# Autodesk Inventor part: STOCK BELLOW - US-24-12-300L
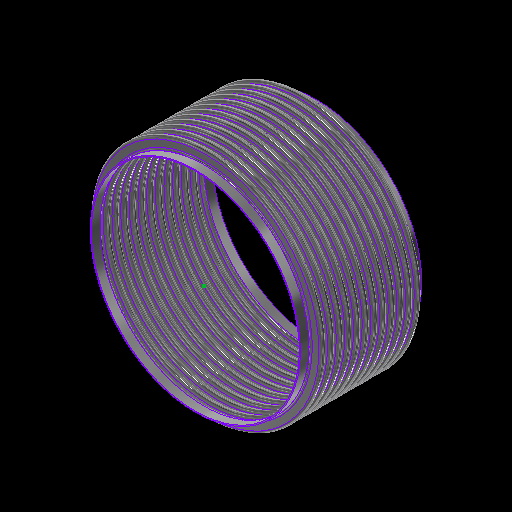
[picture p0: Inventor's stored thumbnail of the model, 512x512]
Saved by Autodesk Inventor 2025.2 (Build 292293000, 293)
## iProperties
Category: 16 GA (0.060 THICK)
RuleStatus: InUse
Created: 2024-01
Part Number: STOCK BELLOW - US-24-12-300L
Project: =STOCK BELLOWS: <Stock Number><SFILL>
Material: ASTM A240-304
Description: =STOCK BELLOWS: <Stock Number>, <SID_> I.D., <SOD_> O.D., <SPLY_> PLY, <Category>, <SNET_CONS> CONS.<PITCH_><STANGENT_> TANGENT<SFILL>
Document SubType Name: Sheet Metal
Designer: GS
Stock Number: U.S-24-12-300L
Surface Area: 40335 cm^2
Volume: 6093.4 cm^3
Sheet Metal Rule: Default
Appearance: STAINLESS STEEL
Mass: 49096.3 g
Density: 8.05729 g/cm^3
THK: 0.036
ID: 3.500
OD: 4.250
CONS_: 2
PITCH: 0.500
TANGENT: 0.500
BELLOWS_UPSET: 0.000
d79: 1.000
d82: 1.000
d83: 26.000
d84: 24.000
d174: 8
d214: 8
STHK_: 0.060
SID_: 24.000
SOD_: 26.750
SPITCH_: 1.000
STANGENT__: 1.000
SBELLOWS_UPSET_: 0.000
SDIFF_TAN: 1.000
d252: 2
d275: 2
d287: 0.050
d289: 0.500
d290: 0.000
SOD_NECK: 24 1/4
PLY: 1
PSET: 4.178
PBAR: 1.035
COUNTER: 1.500
NET_TUBE: 3.071
CONS: 2
S_CONS: 0
NET_CONS: 2
ID_M: 88.90 mm
OD_M: 107.95 mm
THK_M: 0.91 mm
ID_U: 3.500 in
OD_U: 4.250 in
THK_U: 0.036 in
TANGENT2: 0.500
TAN_TO_TAN: 1.000 in
d80: 2.571
d81: 10
SID: 2.375
SCONS_: 12
SPITCH: 0.250
STANGENT_: 1.000
SBELLOWS_UPSET: 0.000
SNET_CONS: 12
SS_CONS: 0
SCONS: 8
d190: 8
d191: 1
d192: 1
d193: 8
d194: 0
SIZE: 24.00
PRESSURE: 300
d230: 8
STANGENT: 4.000
SPLY_: 2
d233: 8
d234: 0
d263: 2
d265: 1
d268: 2
d269: 0
d286: 2
d288: 1
d291: 2
d292: 0
SREROLL: 0.750
BLETP: 1.000 ul
PRES_Copy: 85
MATTABLE: 20 GA (0.036 THICK)
PART_NUMBER: U.S-24-12-300L
PITCH_: =, <SPITCH_> PITCH,
CFILL: .
SFILL: .
MESH: ,
COMP: 2.41
EXT: 1.21
LAT: 0.35
ANG: 573
ASR: 6931
LSR: 46487
ANSR: 9736
PRES: 300
COMPM: 24.1
EXTM: 12.05
LATM: 3.50
ASRM: 1213.826
PRESM: 20.684
LSRM: 8141.268
ANSRM: 1705.066
TEMPMIN: 20
TEMPMAX: 800
TEMPMINM: -7
TEMPMAXM: 427
WEIGHTM: 49.096
WEIGHT: 108.239
Author: GS
Keywords: 20 GA (0.036 THICK)
Comments: =STOCK BELLOW - <STOCK NUMBER>
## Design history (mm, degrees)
sketch "Sketch2"
  geometry: L1 (0, -177.245)-(0, 562.856) reference; L2 (45.364, 0)-(44.45, 0); L3 (48.082, -2.718)-(50.343, -2.718); L4 (48.082, -3.632)-(50.343, -3.632); L5 (50.343, -9.982)-(48.082, -9.982); L6 (50.343, -9.068)-(48.082, -9.068); L7 (45.364, -12.7)-(44.45, -12.7); L8 (48.082, 0)-(48.082, -12.7); L9 (50.343, -6.35)-(53.975, -6.35); L10 (44.45, 0)-(44.45, -12.7); L11 (20.376, 102.841)-(20.376, 101.926); L12 (58.262, 457.127)-(58.262, 349.177); L13 (58.262, 444.427)-(58.262, 336.477); L14 (93.133, -58.817)-(93.133, -71.517); L15 (118.746, -66.401)-(118.746, -66.401); L16 (50.343, -9.068)-(50.343, -9.982); L17 (48.082, -9.068)-(48.082, -9.982); L18 (48.082, -9.525)-(50.343, -9.525); L19 (53.975, 0)-(53.975, -12.7); L20 (-50.343, -9.068)-(-50.343, -9.982); L21 (-50.343, -2.718)-(-48.082, -2.718); L22 (-50.343, -3.632)-(-48.082, -3.632); L23 (-48.082, -9.068)-(-50.343, -9.068); L24 (-50.343, -9.525)-(-48.082, -9.525); L25 (-48.082, -9.982)-(-50.343, -9.982); L26 (-48.082, -9.068)-(-48.082, -9.982); L27 (-44.45, 0.653)-(-44.45, -12.047); L28 (-48.082, -6.35)-(-44.45, -6.35); L29 (-50.343, 0.653)-(-50.343, -12.7); L30 (-53.061, 0)-(-53.975, 0); L31 (-53.975, 0)-(-53.975, -12.7); L32 (-53.061, -12.7)-(-53.975, -12.7); A1 r 2.718 centre (48.082, 0) between (45.364, 0) and (48.082, -2.718); A2 r 3.632 centre (48.082, 0) between (44.45, 0) and (48.082, -3.632); A3 r 3.632 centre (50.343, -6.35) between (50.343, -9.982) and (50.343, -2.718); A4 r 2.718 centre (50.343, -6.35) between (50.343, -9.068) and (50.343, -3.632); A5 r 2.718 centre (48.082, -12.7) between (48.082, -9.982) and (45.364, -12.7); A6 r 3.632 centre (48.082, -12.7) between (48.082, -9.068) and (44.45, -12.7); A7 r 3.175 centre (50.343, -6.35) between (50.343, -9.525) and (53.518, -6.35); A8 r 3.175 centre (48.082, -12.7) between (48.082, -9.525) and (44.907, -12.7); A9 r 2.718 centre (-50.343, -12.7) between (-50.343, -9.982) and (-53.061, -12.7); A10 r 2.718 centre (-48.082, -6.35) between (-48.082, -9.068) and (-48.082, -3.632); A11 r 3.175 centre (-48.082, -6.35) between (-48.082, -9.525) and (-44.907, -6.35); A12 r 3.632 centre (-48.082, -6.35) between (-48.082, -9.982) and (-48.082, -2.718); A13 r 3.175 centre (-50.343, -12.7) between (-50.343, -9.525) and (-53.518, -12.7); A14 r 3.632 centre (-50.343, -12.7) between (-50.343, -9.068) and (-53.975, -12.7); A15 r 2.718 centre (-50.343, 0) between (-53.061, 0) and (-50.343, -2.718); A16 r 3.632 centre (-50.343, 0) between (-53.975, 0) and (-50.343, -3.632); 10 further points
  constraints: 62 end point, 38 point on circle, 20 tangent, 16 centre point, 12 parallel, 9 midpoint, 7 vertical, 6 coincident, 6 concentric, 6 point on line, 4 equal radius, 4 perpendicular, 3 horizontal, 1 collinear, 1 horizontal alignment, 10 other
  dimensions: "THK" = 0.9144 distance of L11.start L11.end; "ID" = 88.9 distance of L11.end point (20.376, 13.026); "OD" = 107.95 distance of L12.start L12.end; "PITCH" = 12.7 distance of L12.start L13.start; "TANGENT" = 12.7 distance of L14.start L14.end; "BELLOWS_UPSET" = 0 distance of L15.start L15.end; "d43" = 88.9 diameter of L10 L1 (= ID); "d44" = 107.95 diameter of L9.end L1 (= OD); "d45" = 0.9144 distance between parallel lines of L5 L6 (computed from THK, PLY); "d46" = 3.6322 radius of A3 (computed from PITCH, THK, PLY); "UPSET_PITCH" = 12.7 distance of L2.end L7.end (derived); "SIDEWALL_ANGLE" = 360 deg dimension on L3 L9 (derived); "CON_GAP" = 5.4356 distance of point (48.082, -9.068) point (48.082, -3.632) (derived); "TAN1" = 4.98728 dimension on A8 (derived); "TAN2" = 4.98728 dimension on A7 (derived); "LEG1" = 2.2606 distance of L18.start L18.end (derived); "d278" = 0.9144 distance between parallel lines of L25 L23 (derived); "d279" = 3.6322 radius of A12 (derived); "d280" = 12.7 distance of L30.end L31.end (derived); "d281" = 360 deg dimension on L21 L28 (derived); "d282" = 5.4356 distance of point (-50.343, -9.068) point (-50.343, -3.632) (derived); "d283" = 4.98728 dimension on A13 (derived); "d284" = 4.98728 dimension on A11 (derived); "d285" = 2.2606 distance of L24.start L24.end (derived); "d293" = 88.9 diameter of L27 L1 (derived); "d294" = 107.95 diameter of L31 L1 (derived)
  node "Sketch Rectangular Pattern1" dims "d31" = 25.4, "ID" = 88.9
  node "Sketch Rectangular Pattern2" dims "d39" = 25.4, "PITCH" = 12.7
revolve "CONS" stored, may be unused: angle "d48" = 90 deg
node "BELLOW MIDPLANE"
pattern_linear "Rectangular Pattern2" dims "d52" = 12.7 (= UPSET_PITCH)
sketch "Sketch5"
  geometry: C1 r 45.364 at (0, 0) reference; C2 r 44.45 at (0, 0) reference
extrude "TANGENT" new body sketch "Sketch5" distance "d53" = 12.7 (= TANGENT); taper "d54" = 0 deg
revolve "SAMETAN" stored, may be unused: angle "d65" = 90 deg
revolve "DIFFTAN" stored, may be unused: angle "d70" = 90 deg
sketch "Sketch9"
  geometry: L1 (53.319, 0)-(-53.319, 0) reference; L2 (0, -17.78)-(0, 17.78) reference; L3 (38.085, 0)-(-38.085, 0); L4 (38.085, -11.906)-(38.085, 11.906); L5 (25.385, -11.906)-(25.385, 11.906); L6 (13.15, 11.906)-(13.15, -11.906); L7 (-25.385, -11.906)-(-25.385, 11.906); L8 (-38.085, -11.906)-(-38.085, 11.906); L9 (37.291, -11.906)-(37.291, 11.906); L10 (38.085, -11.906)-(37.291, -11.906); L11 (38.085, 11.906)-(37.291, 11.906); L12 (13.546, 11.906)-(12.753, 11.906); L13 (12.753, 11.906)-(12.753, -11.906); L14 (12.753, -11.906)-(13.546, -11.906); L15 (13.546, -11.906)-(13.546, 11.906); L16 (-13.546, 11.906)-(-13.546, -11.906); L17 (-13.15, 11.906)-(-13.15, -11.906); L18 (-13.546, -11.906)-(-12.753, -11.906); L19 (-12.753, -11.906)-(-12.753, 11.906); L20 (-12.753, 11.906)-(-13.546, 11.906); L21 (-38.085, -11.906)-(-37.291, -11.906); L22 (-37.291, -11.906)-(-37.291, 11.906); L23 (-37.291, 11.906)-(-38.085, 11.906); L24 (-38.085, 11.906)-(-38.085, -11.906); L25 (38.085, -0.397)-(-38.085, -0.397); L26 (-38.085, -0.397)-(-38.085, 0.397); L27 (-38.085, 0.397)-(38.085, 0.397); L28 (38.085, 0.397)-(38.085, -0.397); L29 (-38.085, 11.906)-(38.085, 11.906); L30 (38.085, 11.906)-(38.085, 12.7); L31 (38.085, 12.7)-(-38.085, 12.7); L32 (-38.085, 12.7)-(-38.085, 11.906); L33 (38.085, -11.906)-(-38.085, -11.906); L34 (-38.085, -11.906)-(-38.085, -12.7); L35 (-38.085, -12.7)-(38.085, -12.7); L36 (38.085, -12.7)-(38.085, -11.906); 30 further points
  constraints: 68 end point, 13 midpoint, 13 parallel, 8 horizontal, 7 perpendicular, 6 equal length, 3 point on line, 2 vertical, 14 other
  dimensions: "d115" = 23.8125 distance of L4.start L4.end (derived); "d116" = 12.7 distance between parallel lines of L4 L5 (derived); "d117" = 12.23516 distance between parallel lines of L5 L6 (derived); "d125" = 38.53427 distance between parallel lines of L7 L6 (derived); "d127" = 12.7 distance between parallel lines of L8 L7 (derived); "d128" = 24.93516 distance between parallel lines of L6 L4 (derived); "d130" = 76.16943 distance between parallel lines of L8 L4 (derived); "RULER_THK" = 0.79375 distance between parallel lines of L4 L9; "d135" = 0.79375 distance of L13.end L14.end (derived); "d138" = 26.29911 distance of L13.end L16.end (derived); "d143" = 0.79375 distance of L22.end L8.end (derived); "d144" = 0.79375 distance between parallel lines of L27 L25 (derived)
extrude "RULER" join sketch "Sketch9" distance "d149" = 0.79375 (derived); taper "d150" = 0 deg
extrude "BARS" join sketch "Sketch9" distance "d151" = 0.79375 (derived); taper "d152" = 0 deg
pattern_linear "Rectangular Pattern4" dims "d155" = 26.29911 (derived)
sketch "Sketch13"
  geometry: L1 (93.149, -52.467)-(93.149, -77.867); L2 (307.848, 0)-(304.8, 0); L3 (307.848, -25.4)-(304.8, -25.4); L4 (331.851, -20.574)-(312.674, -20.574); L5 (331.851, -17.526)-(312.674, -17.526); L6 (331.851, -12.7)-(339.725, -12.7); L7 (312.674, -4.826)-(331.851, -4.826); L8 (312.674, 0)-(312.674, -25.4); L9 (304.8, 0)-(304.8, -25.4); L10 (58.254, 183.019)-(58.254, -496.431); L11 (58.254, 157.619)-(58.254, -521.831); L12 (58.254, 106.819)-(58.254, -572.631); L13 (58.254, 81.419)-(58.254, -598.031); L14 (58.254, 56.019)-(58.254, -623.431); L15 (58.254, 30.619)-(58.254, -648.831); L16 (58.254, 5.219)-(58.254, -674.231); L17 (58.254, 132.219)-(58.254, -547.231); L18 (20.376, 103.45)-(20.376, 101.926); L19 (312.674, -7.874)-(331.851, -7.874); L20 (0, -845.681)-(0, 354.469) reference; L21 (-67.945, 0)-(407.67, 0) reference; A1 r 4.826 centre (312.674, 0) between (307.848, 0) and (312.674, -4.826); A2 r 4.826 centre (312.674, -25.4) between (312.674, -20.574) and (307.848, -25.4); A3 r 7.874 centre (312.674, -25.4) between (312.674, -17.526) and (304.8, -25.4); A4 r 4.826 centre (331.851, -12.7) between (331.851, -17.526) and (331.851, -7.874); A5 r 7.874 centre (331.851, -12.7) between (331.851, -20.574) and (331.851, -4.826); A6 r 7.874 centre (312.674, 0) between (304.8, 0) and (312.674, -7.874); 6 further points; 1 other entity
  constraints: 38 end point, 15 point on circle, 9 tangent, 6 centre point, 6 parallel, 5 vertical alignment, 4 point on line, 4 vertical, 3 coincident, 3 concentric, 2 collinear, 2 equal radius, 1 horizontal, 1 perpendicular, 23 other
  dimensions: "SBELLOWS_UPSET_" = 0 distance of point (118.762, -66.401) point (118.762, -66.401); "STOTAL_THK_BELLOW__" = 3.048 distance between parallel lines of L4 L5 (derived); "d224" = 7.874 radius of A5 (derived); "d225" = 25.4 distance of L2.end L3.end (derived); "SSIDEWALL_ANGLE_" = 360 deg dimension on L7 L6 (derived); "SSCON_GAP_" = 9.652 distance of point (312.674, -17.526) point (312.674, -7.874) (derived); "d235" = 609.6 diameter of L9 L20 (derived); "d236" = 679.45 diameter of L6.end L20 (derived)
  node "Sketch Rectangular Pattern4" dims "d228" = 25.4
  node "Sketch Rectangular Pattern5" dims "d229" = 25.4
revolve "SBELLOW" stored, may be unused: angle "d197" = 90 deg
pattern_linear "Rectangular Pattern5" dims "d204" = 25.4 (derived)
revolve "STANGENT" stored, may be unused: angle "d240" = 90 deg
revolve "SSAMETAN" stored, may be unused: angle "d241" = 90 deg
revolve "SDIFFTAN" stored, may be unused: angle "d246" = 90 deg
revolve "INVCON" stored, may be unused: angle "d295" = 90 deg
pattern_linear "Rectangular Pattern6" dims "d298" = 12.7 (derived)
revolve "INVTANGENT" stored, may be unused: angle "d302" = 90 deg
revolve "INVSAMETAN" stored, may be unused: angle "d307" = 90 deg
revolve "INVDIFFTAN" stored, may be unused: angle "d312" = 90 deg
sketch "ID BELLOW MOUNT CALC"
  geometry: L1 (44.45, 0)-(38.1, 0); L2 (38.1, 0)-(38.1, 12.7); L3 (38.1, 12.7)-(44.45, 12.7); L4 (44.45, 12.7)-(44.45, 0); L5 (36.513, 12.7)-(35.598, 12.7); L6 (35.598, 12.7)-(35.598, 0); L7 (35.598, 0)-(36.513, 0); L8 (36.513, 0)-(36.513, 12.7); L9 (0, -2.54)-(0, 15.24) reference; L10 (-8.89, 0)-(53.34, 0) reference; 1 further point
  constraints: 16 end point, 5 parallel, 2 collinear, 2 horizontal, 2 perpendicular
  dimensions: "d314" = 12.7 distance of L5.end L6.end (derived); "d315" = 0.9144 distance of L5.start L5.end (derived); "IG" = 1.5875 distance between parallel lines of L2 L8; "PIPE_OD" = 88.9 diameter of L4 L9; "PIPE_WALL" = 6.35 distance of L2.end L3.end; "ID_MT_BELLOW" = 71.1962 diameter of L6 L9 (derived)
revolve "CFILL" stored, may be unused: angle "d320" = 90 deg
pattern_linear "Rectangular Pattern7" dims "d323" = 12.7 (derived)
revolve "SFILL" stored, may be unused: angle "d324" = 90 deg
pattern_linear "Rectangular Pattern8" dims "d327" = 25.4 (derived)
node "STOCK BELLOW MIDPLANE"
node "BELLOW"
sketch "Sketch6"
  geometry: L1 (-12.7, 45.364)-(0, 45.364); L2 (0, 45.364)-(0, 44.45); L3 (0, 44.45)-(-12.7, 44.45); L4 (-12.7, 44.45)-(-12.7, 45.364); L5 (10.16, 0)-(-60.96, 0) reference; L6 (-38.1, -89.422)-(-38.1, 153.44) reference; 1 further point
  constraints: 8 end point, 2 parallel, 1 horizontal, 1 perpendicular
  dimensions: "d61" = 12.7 distance of L2.end L3.end (derived); "d62" = 0.9144 distance of L1.end L2.end (derived); "d63" = 88.9 diameter of L3 L5 (derived); "d64" = 25.4 distance between parallel lines of L4 L6 (derived)
sketch "Sketch12"
  geometry: 1 further point
sketch "Sketch14"
  geometry: L1 (-25.4, 307.848)-(0, 307.848); L2 (0, 307.848)-(0, 304.8); L3 (0, 304.8)-(-25.4, 304.8); L4 (-25.4, 304.8)-(-25.4, 307.848); L5 (5.08, 0)-(-30.48, 0) reference; L6 (0, -61.57)-(0, 369.418) reference; 1 further point
  constraints: 8 end point, 2 parallel, 1 collinear, 1 horizontal, 1 perpendicular
  dimensions: "d237" = 3.048 distance of L3.end L1.start (derived); "d238" = 609.6 diameter of L3 L5 (derived); "d239" = 25.4 distance of L1.start L1.end (derived); "SOD_NECK" = 615.696 diameter of L1 L5 (derived)
sketch "Sketch15"
  geometry: L1 (-61.57, 0)-(369.418, 0) reference; L2 (304.8, -304.8)-(307.848, -304.8); L3 (307.848, -304.8)-(307.848, -330.2); L4 (307.848, -330.2)-(304.8, -330.2); L5 (304.8, -330.2)-(304.8, -304.8); L6 (0, -398.78)-(0, 81.28) reference; 1 further point
  constraints: 8 end point, 2 parallel, 1 horizontal, 1 perpendicular
  dimensions: "d205" = 25.4 distance of L4.end L2.start (derived); "d206" = 3.048 distance of L3.end L4.end (derived); "d207" = 609.6 diameter of L5 L6 (derived); "d208" = 304.8 distance between parallel lines of L1 L2 (derived)
node "TANGENT_"
node "SAME_TAN"
sketch "Sketch8"
  geometry: L1 (45.364, -25.4)-(44.45, -25.4); L2 (44.45, -25.4)-(44.45, -38.1); L3 (44.45, -38.1)-(45.364, -38.1); L4 (45.364, -38.1)-(45.364, -25.4); L5 (0, -48.26)-(0, 22.86) reference; L6 (-89.422, 0)-(153.44, 0) reference; 1 further point
  constraints: 8 end point, 2 parallel, 1 horizontal, 1 perpendicular
  dimensions: "d66" = 88.9 diameter of L2 L5 (derived); "TOTAL_THK_BELLOW" = 0.9144 distance of L2.end L3.end (derived); "d68" = 25.4 distance between parallel lines of L1 L6 (derived); "d69" = 12.7 distance of L1.end L2.end (derived)
node "DIFF_TAN"
node "Sketch Rectangular Pattern3" dims "d138" = 26.29911 (derived), "d141" = 25.4
node "SBELLOW_"
node "STANGENT_"
node "SSAME_TAN"
sketch "Sketch16"
  geometry: L1 (307.848, -304.8)-(304.8, -304.8); L2 (304.8, -304.8)-(304.8, -330.2); L3 (304.8, -330.2)-(307.848, -330.2); L4 (307.848, -330.2)-(307.848, -304.8); L5 (0, -398.78)-(0, 81.28) reference; L6 (-61.57, 0)-(369.418, 0) reference; 1 further point
  constraints: 8 end point, 2 parallel, 1 horizontal, 1 perpendicular
  dimensions: "SDIFF_TAN" = 25.4 distance of L3.end L1.start; "d243" = 3.048 distance of L2.end L3.end (derived); "d244" = 304.8 distance between parallel lines of L1 L6 (derived); "d245" = 609.6 diameter of L2 L5 (derived)
node "SDIFF_TAN"
body "Solid15"
sketch "Sketch17"
  geometry: L1 (53.975, 12.7)-(53.061, 12.7); L2 (53.061, 12.7)-(53.061, 0); L3 (53.061, 0)-(53.975, 0); L4 (53.975, 0)-(53.975, 12.7); L5 (0, -2.54)-(0, 15.24) reference; L6 (-10.795, 0)-(64.77, 0) reference; 2 further points
  constraints: 8 end point, 2 parallel, 1 horizontal, 1 midpoint, 1 perpendicular, 1 point on line
  dimensions: "INVTANGENT" = 12.7 distance of L3.end L1.start (derived); "d300" = 0.9144 distance of L1.start L1.end (derived); "d301" = 107.95 diameter of L4 L5 (derived)
body "Solid16"
sketch "Sketch18"
  geometry: L1 (53.975, -25.4)-(53.061, -25.4); L2 (53.061, -25.4)-(53.061, -38.1); L3 (53.061, -38.1)-(53.975, -38.1); L4 (53.975, -38.1)-(53.975, -25.4); L5 (-10.795, 0)-(64.77, 0) reference; L6 (0, -48.26)-(0, 22.86) reference; 1 further point
  constraints: 8 end point, 2 parallel, 1 horizontal, 1 perpendicular
  dimensions: "d303" = 25.4 distance between parallel lines of L1 L5 (derived); "d304" = 12.7 distance of L3.end L1.start (derived); "d305" = 0.9144 distance of L2.end L3.end (derived); "d306" = 107.95 diameter of L4 L6 (derived)
body "Solid17"
sketch "Sketch19"
  geometry: L1 (53.975, -25.4)-(53.061, -25.4); L2 (53.061, -25.4)-(53.061, -38.1); L3 (53.061, -38.1)-(53.975, -38.1); L4 (53.975, -38.1)-(53.975, -25.4); L5 (0, -48.26)-(0, 22.86) reference; L6 (-10.795, 0)-(64.77, 0) reference; 1 further point
  constraints: 8 end point, 2 parallel, 1 horizontal, 1 perpendicular
  dimensions: "d308" = 12.7 distance of L1.end L2.end (derived); "d309" = 107.95 diameter of L4 L5 (derived); "d310" = 0.9144 distance of L2.end L3.end (derived); "d311" = 25.4 distance between parallel lines of L1 L6 (derived)
body "Solid18"
body "Solid19"
body "Solid20"
other parameters: "BMPL" = -152.4, "PSET" = 106.1212 (computed from OD, THK, PLY) [user parameter], "PBAR" = 26.29911 (= 0.570796 x PITCH + OD - ID) [user parameter; used in 1 equation term], "COUNTER" = 15 [user parameter], "NET_TUBE" = 77.99823 (computed from CONS_, PBAR, TANGENT) [user parameter], "S_CONS" = 0 [user parameter; used in 1 equation term], "ID_M" = 88.9 (= ID) [user parameter], "OD_M" = 107.95 (= OD) [user parameter], "THK_M" = 0.9144 (= THK) [user parameter], "ID_U" = 88.9 (= ID) [user parameter], "OD_U" = 107.95 (= OD) [user parameter], "THK_U" = 0.9144 (= THK) [user parameter], "D_UNITS" = 0 [user parameter], "TANGENT2" = 12.7 [user parameter], "TAN_TO_TAN" = 25.4 [user parameter], "OD_NECK" = 90.7288 [user parameter], "d79" = 25.4, "d80" = 65.29823 [user parameter], "d82" = 25.4, "d83" = 660.4, "d84" = 609.6, "sa_0" = 4, "FRAME_THK" = 0.79375 [user parameter], "CON_FLAT" = 12.23516 [user parameter], "SID" = 60.325 [user parameter], "SPITCH" = 6.35 [user parameter], "STANGENT_" = 25.4 [user parameter], "SBELLOWS_UPSET" = 0 [user parameter], "SS_CONS" = 0 [user parameter], "STAN_TO_TAN_" = 304.8 [user parameter], "d100" = 3.048 [user parameter], "d191" = 25.4 [user parameter], "d194" = 0 [user parameter], "STANGENT" = 101.6 [user parameter], "d234" = 0 [user parameter], "SUPSET_PITCH_" = 25.4 [user parameter], "d269" = 0 [user parameter], "d287" = 1.27, "d289" = 12.7, "d290" = 0, "d292" = 0 [user parameter], "Thickness" = 3.048 (derived), "KFactor" = 4.4, "BendRadius" = 3.048 (derived), "BendReliefWidth" = 3.048 (derived), "BendReliefDepth" = 1.524 (derived), "CornerReliefSize" = 12.192 (derived), "SeamGap" = 0.00508, "MinimumRemnant" = 6.096 (derived), "TransitionRadius" = 3.048 (derived), "JacobiRadiusSize" = 3.048 (derived), "GapSize" = 3.048 (derived), "SREROLL" = 19.05 [user parameter], "CUR_STK_PITCH" = 25.4 [user parameter], "d328" = -152.4 (derived), "ASR" = 69310 [user parameter], "LSR" = 464870 [user parameter], "ANSR" = 97360 [user parameter], "BLETP" = 1 [user parameter], "ASRM" = 12138.2603 [user parameter], "PRESM" = 206.83949 [user parameter], "LSRM" = 81412.6831 [user parameter], "ANSRM" = 17050.6568 [user parameter], "TEMPMIN" = 2664.83333 [user parameter], "TEMPMAX" = 6998.16667 [user parameter], "TEMPMINM" = 2664.83333 [user parameter], "TEMPMAXM" = 6998.16667 [user parameter], "WEIGHT" = 490.96309 [user parameter], "WEIGHTM" = 0.49096 [user parameter]
